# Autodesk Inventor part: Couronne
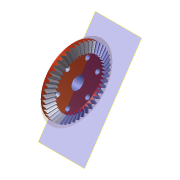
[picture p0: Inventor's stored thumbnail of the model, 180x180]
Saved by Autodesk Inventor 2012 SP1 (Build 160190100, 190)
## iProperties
Created: 2014-12
Part Number: Couronne
Material: Default
Document SubType Name: Modeling
Designer: Bruno
Density: 1 g/cm^3
Mass: 4.64772 g
Surface Area: 44.5223 cm^2
Volume: 4.64772 cm^3
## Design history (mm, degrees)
node "Couronne1"
node "Plan de construction8"
sketch "Esquisse7"
  geometry: L1 (-24.269, -7.937)-(-16.349, -5.551); L2 (4.75, -13.063)-(-4.75, -13.063) reference; L3 (0, -13.063)-(0, -4.631); 1 further point
  constraints: 4 end point, 1 midpoint, 1 perpendicular
feature "SrfRévolution1" sketch "Esquisse7" dims angle "d15" = 90 deg
node "Couronne"
node "Base1"
body "Srf1"
